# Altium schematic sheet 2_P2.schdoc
size 431 x 309 mm; Symbol: Sheet-Symbol_A3; Device: Sheet-Symbol_A3; Company: PCBCrew.com; Drawed: DumTux; Reviewed: EasyEDA Pro; Version: V0.1; Page Size: A3; @Project Name: BLDGOT ESP32 Temperature Controller; @Page Count: 2; @Update Date: 2023-02-26; @Create Date: 2023-02-25; @Schematic Name: Temperature Controller; Part Number: JLCPCB-001; @Page No: 2; @Page Name: P2
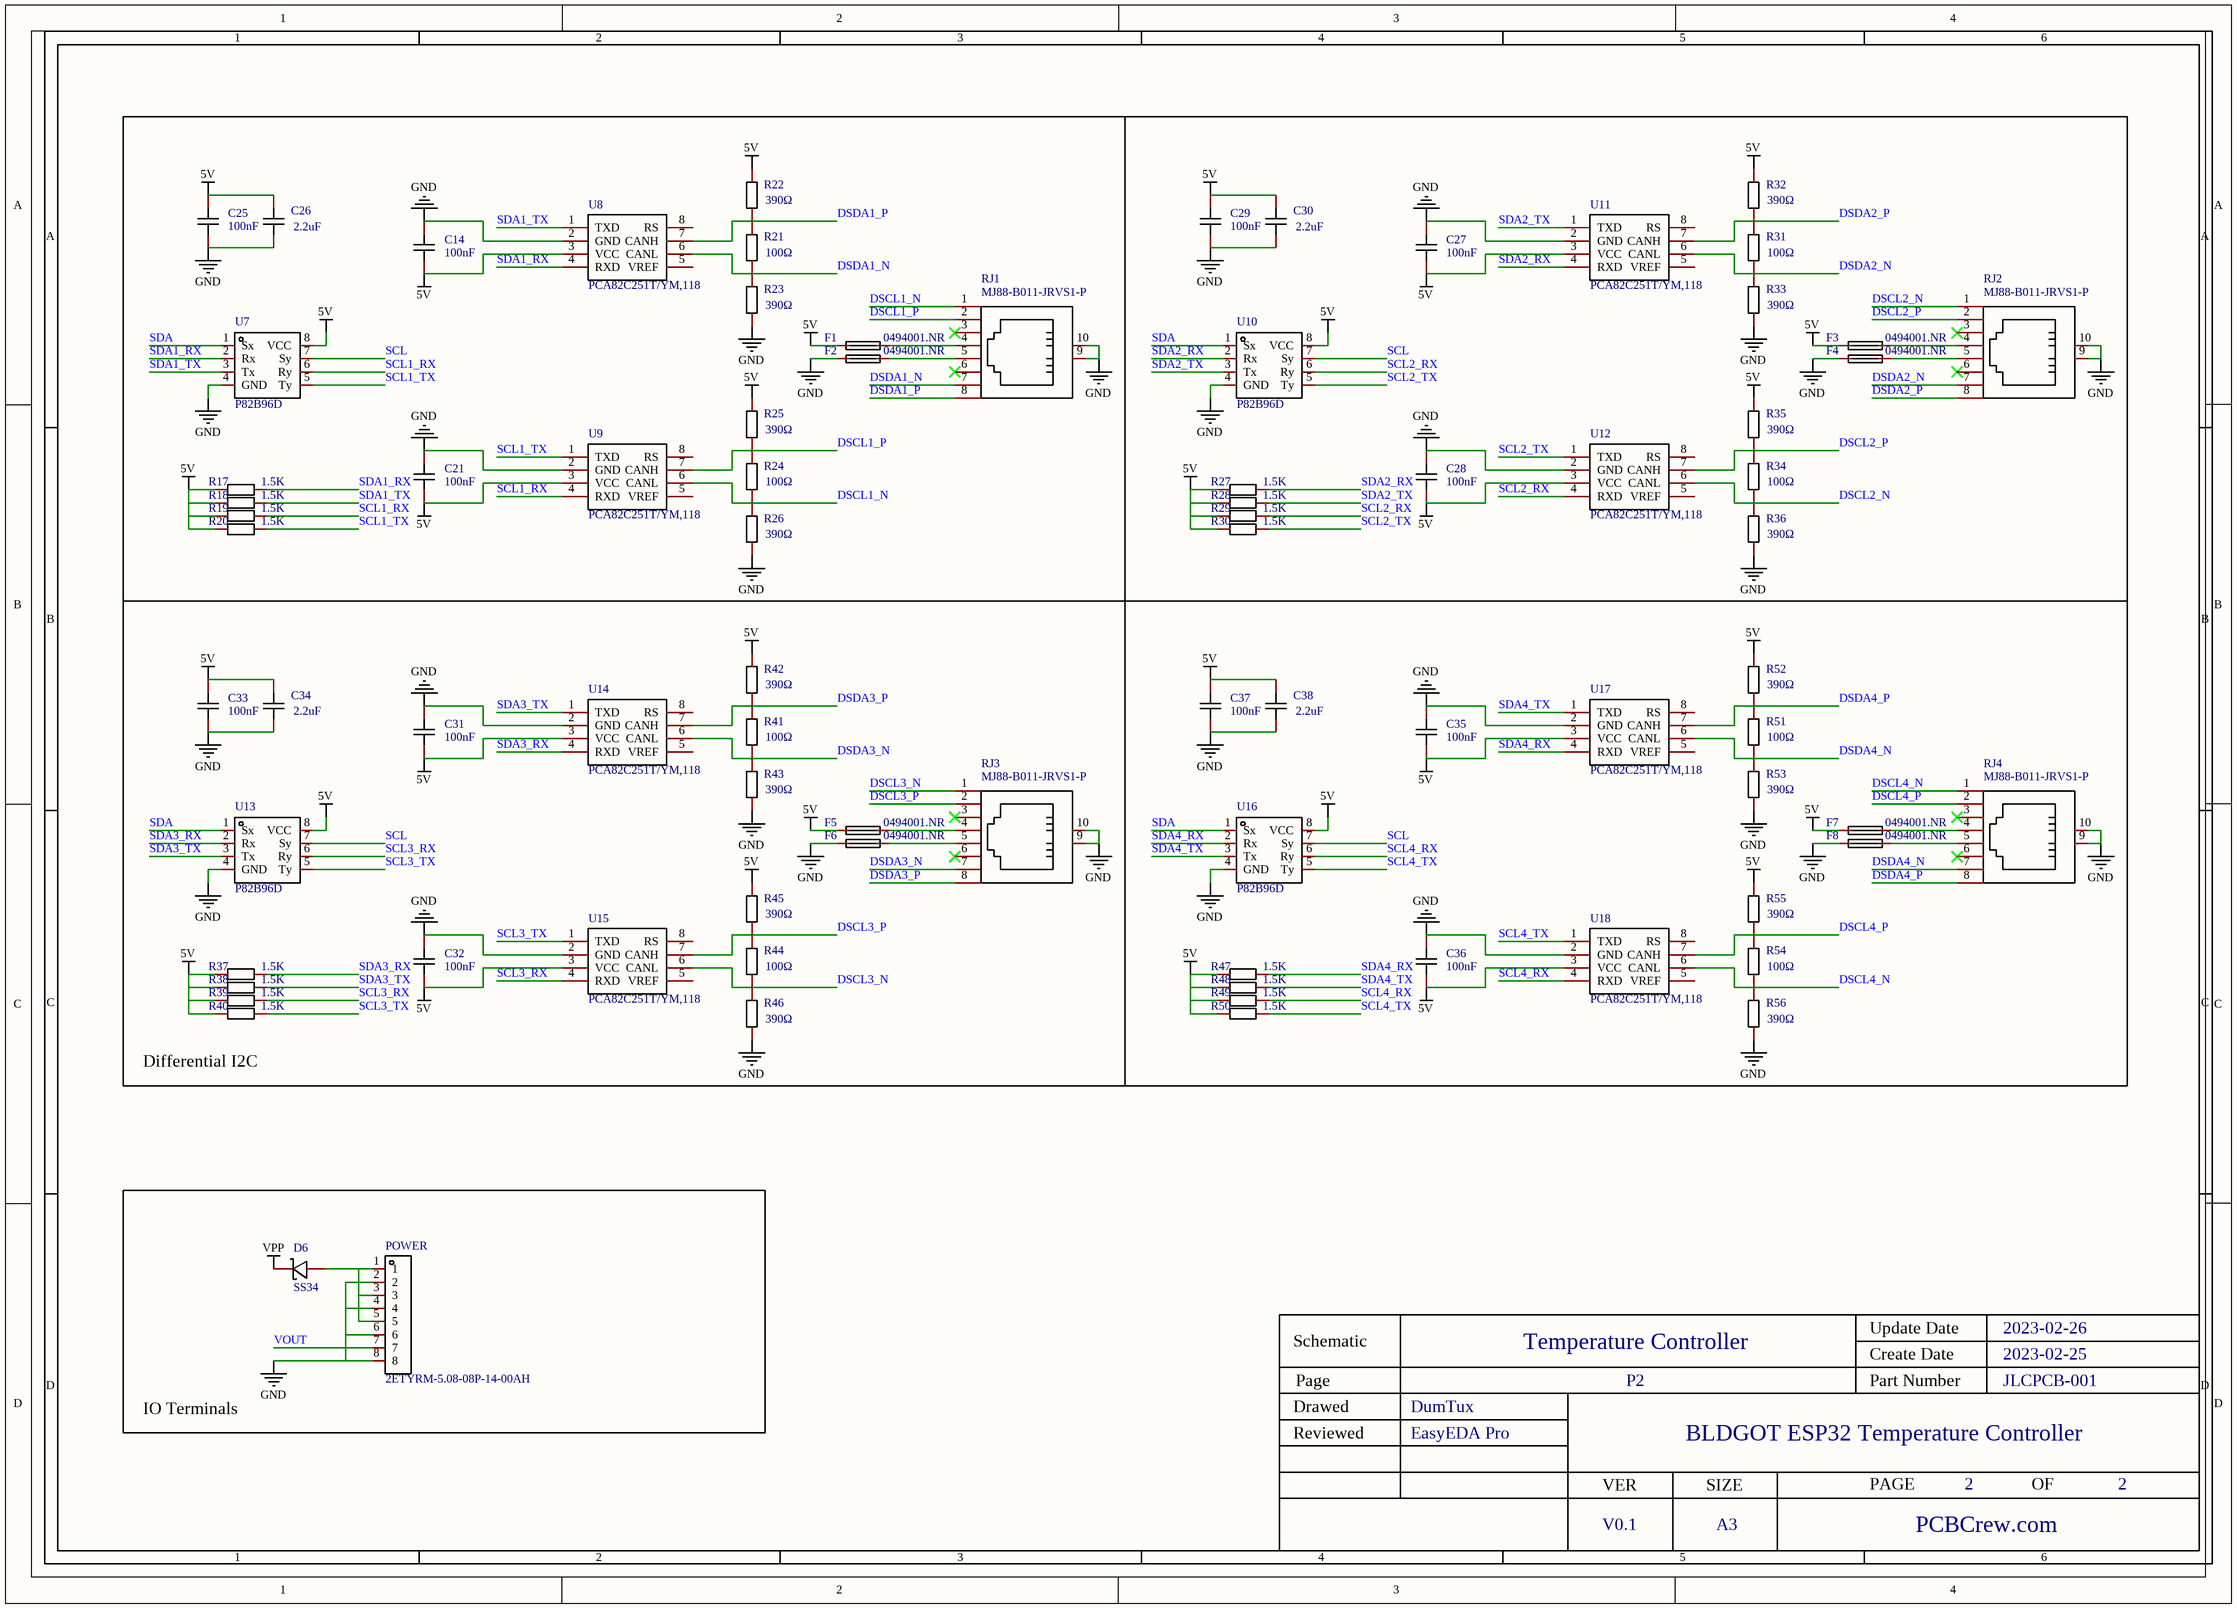
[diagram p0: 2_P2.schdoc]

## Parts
C14  100nF  [C0402]
C21  100nF  [C0402]
C25  100nF  [C0402]
C26  2.2uF  [C0402]
C27  100nF  [C0402]
C28  100nF  [C0402]
C29  100nF  [C0402]
C30  2.2uF  [C0402]
C31  100nF  [C0402]
C32  100nF  [C0402]
C33  100nF  [C0402]
C34  2.2uF  [C0402]
C35  100nF  [C0402]
C36  100nF  [C0402]
C37  100nF  [C0402]
C38  2.2uF  [C0402]
D6  SS34  [SMA_L4.3-W2.6-LS5.2-RD]
F1  0494001.NR  [F0603]
F2  0494001.NR  [F0603]
F3  0494001.NR  [F0603]
F4  0494001.NR  [F0603]
F5  0494001.NR  [F0603]
F6  0494001.NR  [F0603]
F7  0494001.NR  [F0603]
F8  0494001.NR  [F0603]
POWER  2ETYRM-5.08-08P-14-00AH  [CONN-TH_2ETYRM-5.08-08P-14-00AH]
R17  1.5K  [R0402]
R18  1.5K  [R0402]
R19  1.5K  [R0402]
R20  1.5K  [R0402]
R21  100Ω  [R0603]
R22  390Ω  [R0603]
R23  390Ω  [R0603]
R24  100Ω  [R0603]
R25  390Ω  [R0603]
R26  390Ω  [R0603]
R27  1.5K  [R0402]
R28  1.5K  [R0402]
R29  1.5K  [R0402]
R30  1.5K  [R0402]
R31  100Ω  [R0603]
R32  390Ω  [R0603]
R33  390Ω  [R0603]
R34  100Ω  [R0603]
R35  390Ω  [R0603]
R36  390Ω  [R0603]
R37  1.5K  [R0402]
R38  1.5K  [R0402]
R39  1.5K  [R0402]
R40  1.5K  [R0402]
R41  100Ω  [R0603]
R42  390Ω  [R0603]
R43  390Ω  [R0603]
R44  100Ω  [R0603]
R45  390Ω  [R0603]
R46  390Ω  [R0603]
R47  1.5K  [R0402]
R48  1.5K  [R0402]
R49  1.5K  [R0402]
R50  1.5K  [R0402]
R51  100Ω  [R0603]
R52  390Ω  [R0603]
R53  390Ω  [R0603]
R54  100Ω  [R0603]
R55  390Ω  [R0603]
R56  390Ω  [R0603]
RJ1  MJ88-B011-JRVS1-P  [RJ45-SMD_MJ88-B011-JRVS1-P.]
RJ2  MJ88-B011-JRVS1-P  [RJ45-SMD_MJ88-B011-JRVS1-P.]
RJ3  MJ88-B011-JRVS1-P  [RJ45-SMD_MJ88-B011-JRVS1-P.]
RJ4  MJ88-B011-JRVS1-P  [RJ45-SMD_MJ88-B011-JRVS1-P.]
U7  P82B96D  [SOIC-8_L5.0-W4.0-P1.27-LS6.1-BL]
U8  PCA82C251T/YM,118  [SOIC-8_L5.0-W4.0-P1.27-LS6.0-BL]
U9  PCA82C251T/YM,118  [SOIC-8_L5.0-W4.0-P1.27-LS6.0-BL]
U10  P82B96D  [SOIC-8_L5.0-W4.0-P1.27-LS6.1-BL]
U11  PCA82C251T/YM,118  [SOIC-8_L5.0-W4.0-P1.27-LS6.0-BL]
U12  PCA82C251T/YM,118  [SOIC-8_L5.0-W4.0-P1.27-LS6.0-BL]
U13  P82B96D  [SOIC-8_L5.0-W4.0-P1.27-LS6.1-BL]
U14  PCA82C251T/YM,118  [SOIC-8_L5.0-W4.0-P1.27-LS6.0-BL]
U15  PCA82C251T/YM,118  [SOIC-8_L5.0-W4.0-P1.27-LS6.0-BL]
U16  P82B96D  [SOIC-8_L5.0-W4.0-P1.27-LS6.1-BL]
U17  PCA82C251T/YM,118  [SOIC-8_L5.0-W4.0-P1.27-LS6.0-BL]
U18  PCA82C251T/YM,118  [SOIC-8_L5.0-W4.0-P1.27-LS6.0-BL]

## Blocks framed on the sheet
Differential I2C: C31-C34 F5 F6 R37-R46 RJ3 U13-U15
IO Terminals: D6 POWER

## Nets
5V: C14.2 C21.2 C25.2 C26.1 C27.2 C28.2 C29.2 C30.1 C31.2 C32.2 C33.2 C34.1 C35.2 C36.2 C37.2 C38.1 F1.1 F3.1 F5.1 F7.1 R17.2 R18.2 R19.2 R20.2 R22.2 R25.2 R27.2 R28.2 R29.2 R30.2 R32.2 R35.2 R37.2 R38.2 R39.2 R40.2 R42.2 R45.2 R47.2 R48.2 R49.2 R50.2 R52.2 R55.2 U7.8(VCC) U8.3(VCC) U9.3(VCC) U10.8(VCC) U11.3(VCC) U12.3(VCC) U13.8(VCC) U14.3(VCC) U15.3(VCC) U16.8(VCC) U17.3(VCC) U18.3(VCC)
GND: C14.1 C21.1 C25.1 C26.2 C27.1 C28.1 C29.1 C30.2 C31.1 C32.1 C33.1 C34.2 C35.1 C36.1 C37.1 C38.2 F2.1 F4.1 F6.1 F8.1 POWER.2 POWER.4 POWER.6 POWER.8 R23.1 R26.1 R33.1 R36.1 R43.1 R46.1 R53.1 R56.1 RJ1.9(SHELL) RJ1.10(SHELL) RJ2.9(SHELL) RJ2.10(SHELL) RJ3.9(SHELL) RJ3.10(SHELL) RJ4.9(SHELL) RJ4.10(SHELL) U7.4(GND) U8.2(GND) U9.2(GND) U10.4(GND) U11.2(GND) U12.2(GND) U13.4(GND) U14.2(GND) U15.2(GND) U16.4(GND) U17.2(GND) U18.2(GND)
VPP: D6.1(K)
DSCL1_N: R24.1 R26.2 RJ1.1 U9.6(CANL)
DSCL1_P: R24.2 R25.1 RJ1.2 U9.7(CANH)
DSCL2_N: R34.1 R36.2 RJ2.1 U12.6(CANL)
DSCL2_P: R34.2 R35.1 RJ2.2 U12.7(CANH)
DSCL3_N: R44.1 R46.2 RJ3.1 U15.6(CANL)
DSCL3_P: R44.2 R45.1 RJ3.2 U15.7(CANH)
DSCL4_N: R54.1 R56.2 RJ4.1 U18.6(CANL)
DSCL4_P: R54.2 R55.1 RJ4.2 U18.7(CANH)
DSDA1_N: R21.1 R23.2 RJ1.7 U8.6(CANL)
DSDA1_P: R21.2 R22.1 RJ1.8 U8.7(CANH)
DSDA2_N: R31.1 R33.2 RJ2.7 U11.6(CANL)
DSDA2_P: R31.2 R32.1 RJ2.8 U11.7(CANH)
DSDA3_N: R41.1 R43.2 RJ3.7 U14.6(CANL)
DSDA3_P: R41.2 R42.1 RJ3.8 U14.7(CANH)
DSDA4_N: R51.1 R53.2 RJ4.7 U17.6(CANL)
DSDA4_P: R51.2 R52.1 RJ4.8 U17.7(CANH)
SCL: U7.7(Sy) U10.7(Sy) U13.7(Sy) U16.7(Sy)
SCL1_RX: R19.1 U7.6(Ry) U9.4(RXD)
SCL1_TX: R20.1 U7.5(Ty) U9.1(TXD)
SCL2_RX: R29.1 U10.6(Ry) U12.4(RXD)
SCL2_TX: R30.1 U10.5(Ty) U12.1(TXD)
SCL3_RX: R39.1 U13.6(Ry) U15.4(RXD)
SCL3_TX: R40.1 U13.5(Ty) U15.1(TXD)
SCL4_RX: R49.1 U16.6(Ry) U18.4(RXD)
SCL4_TX: R50.1 U16.5(Ty) U18.1(TXD)
SDA: U7.1(Sx) U10.1(Sx) U13.1(Sx) U16.1(Sx)
SDA1_RX: R17.1 U7.2(Rx) U8.4(RXD)
SDA1_TX: R18.1 U7.3(Tx) U8.1(TXD)
SDA2_RX: R27.1 U10.2(Rx) U11.4(RXD)
SDA2_TX: R28.1 U10.3(Tx) U11.1(TXD)
SDA3_RX: R37.1 U13.2(Rx) U14.4(RXD)
SDA3_TX: R38.1 U13.3(Tx) U14.1(TXD)
SDA4_RX: R47.1 U16.2(Rx) U17.4(RXD)
SDA4_TX: R48.1 U16.3(Tx) U17.1(TXD)
VOUT: POWER.7
NetD6_2: D6.2(A) POWER.1 POWER.3 POWER.5
NetF1_2: F1.2 RJ1.4
NetF2_2: F2.2 RJ1.5
NetF3_2: F3.2 RJ2.4
NetF4_2: F4.2 RJ2.5
NetF5_2: F5.2 RJ3.4
NetF6_2: F6.2 RJ3.5
NetF7_2: F7.2 RJ4.4
NetF8_2: F8.2 RJ4.5

Not connected (* = marked no-connect by the designer): RJ1 3* 6*; RJ2 3* 6*; RJ3 3* 6*; RJ4 3* 6*; U8 5(VREF) 8(RS); U9 5(VREF) 8(RS); U11 5(VREF) 8(RS); U12 5(VREF) 8(RS); U14 5(VREF) 8(RS); U15 5(VREF) 8(RS); U17 5(VREF) 8(RS); U18 5(VREF) 8(RS)

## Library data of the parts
C14 C21 C25-C38 = CAP_0402: Symbol: CAP; Convert to PCB: yes
D6 = SS34_C8678: Diode Configuration:Single Reverse Voltage (Vr):40V Average Rectified Current (Io):3A Forward Voltage (Vf@If):0.55V@3A Reverse Leakage Current (Ir):0.5mA@40V; Manufacturer: MDD; Add into BOM: yes; Diode Configuration: Single; Reverse Voltage (Vr): 40V; Average Rectified Current (Io): 3A
F1-F8 = 0494001.NR: Type:SMD Fuse Current Rating:1A Voltage Rating  (AC):32V Voltage Rating (DC):32V Breaking Capacity:50A Operating Temperature:-50℃~+90℃ Operating Temperature:-50℃~+90℃; Manufacturer: Littelfuse(美国力特); Add into BOM: yes; Current Rating: 1A; Voltage Rating  (AC): 32V; Breaking Capacity: 50A
POWER = 2ETYRM-5.08-08P-14-00AH: Connector Type:板端/Receptacle-Close Pitch:5.08mm Number of Rows:1 Number of PINs Per Row:8 Mounting Style:Bend Current Rating (Max):15A Voltage Rating (Max):300V Contact Material:Copper Contact Plating:Tin Operating Temperature Range:-40℃~+105℃ Operating T; Manufacturer: Toponelec(拓宜); Add into BOM: yes; Pitch: 5.08mm; Number of PINs Per Row: 8; Current Rating (Max): 15A; Voltage Rating (Max): 300V; Welding Temperature (Max): 265℃@2~3S; fixed form: Screw fixed
R17-R20 R27-R30 R37-R40 R47-R50 = Res_0402: Symbol: Res; Convert to PCB: yes
R21-R26 R31-R36 R41-R46 R51-R56 = Res_0603: Symbol: Res; Convert to PCB: yes
RJ1-RJ4 = MJ88-B011-JRVS1-P: Connector Type:RJReceptacle USOC Codes:RJ45 Number of Ports:1 Ratings:- Mounting Style:Sink board Shielding:有 LED:不带LED Operating Temperature Range:-40℃~+80℃ Operating Temperature Range:-40℃~+80℃; Manufacturer: Heling(合陵); Add into BOM: yes; USOC Codes: RJ45; Number of Ports: 1; Shielding: 有; LED: 不带LED
U7 U10 U13 U16 = P82B96D: Manufacturer: TI(德州仪器); Add into BOM: yes
U8 U9 U11 U12 U14 U15 U17 U18 = PCA82C251T/YM,118: Type:Transceiver Supply Voltage:4.5V~5.5V Supply Voltage:4.5V~5.5V; Manufacturer: NXP(恩智浦); Add into BOM: yes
